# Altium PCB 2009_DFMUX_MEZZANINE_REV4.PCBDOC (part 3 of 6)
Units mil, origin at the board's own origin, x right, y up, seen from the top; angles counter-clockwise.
Board outline 4922.86 x 3627.76 mil, 6 copper layers (Top Layer, Internal Plane 1, Mid-Layer 1, Internal Plane 2, Mid-Layer 2, Bottom Layer); 519 components, 606 nets, 2175 pads, 757 vias.
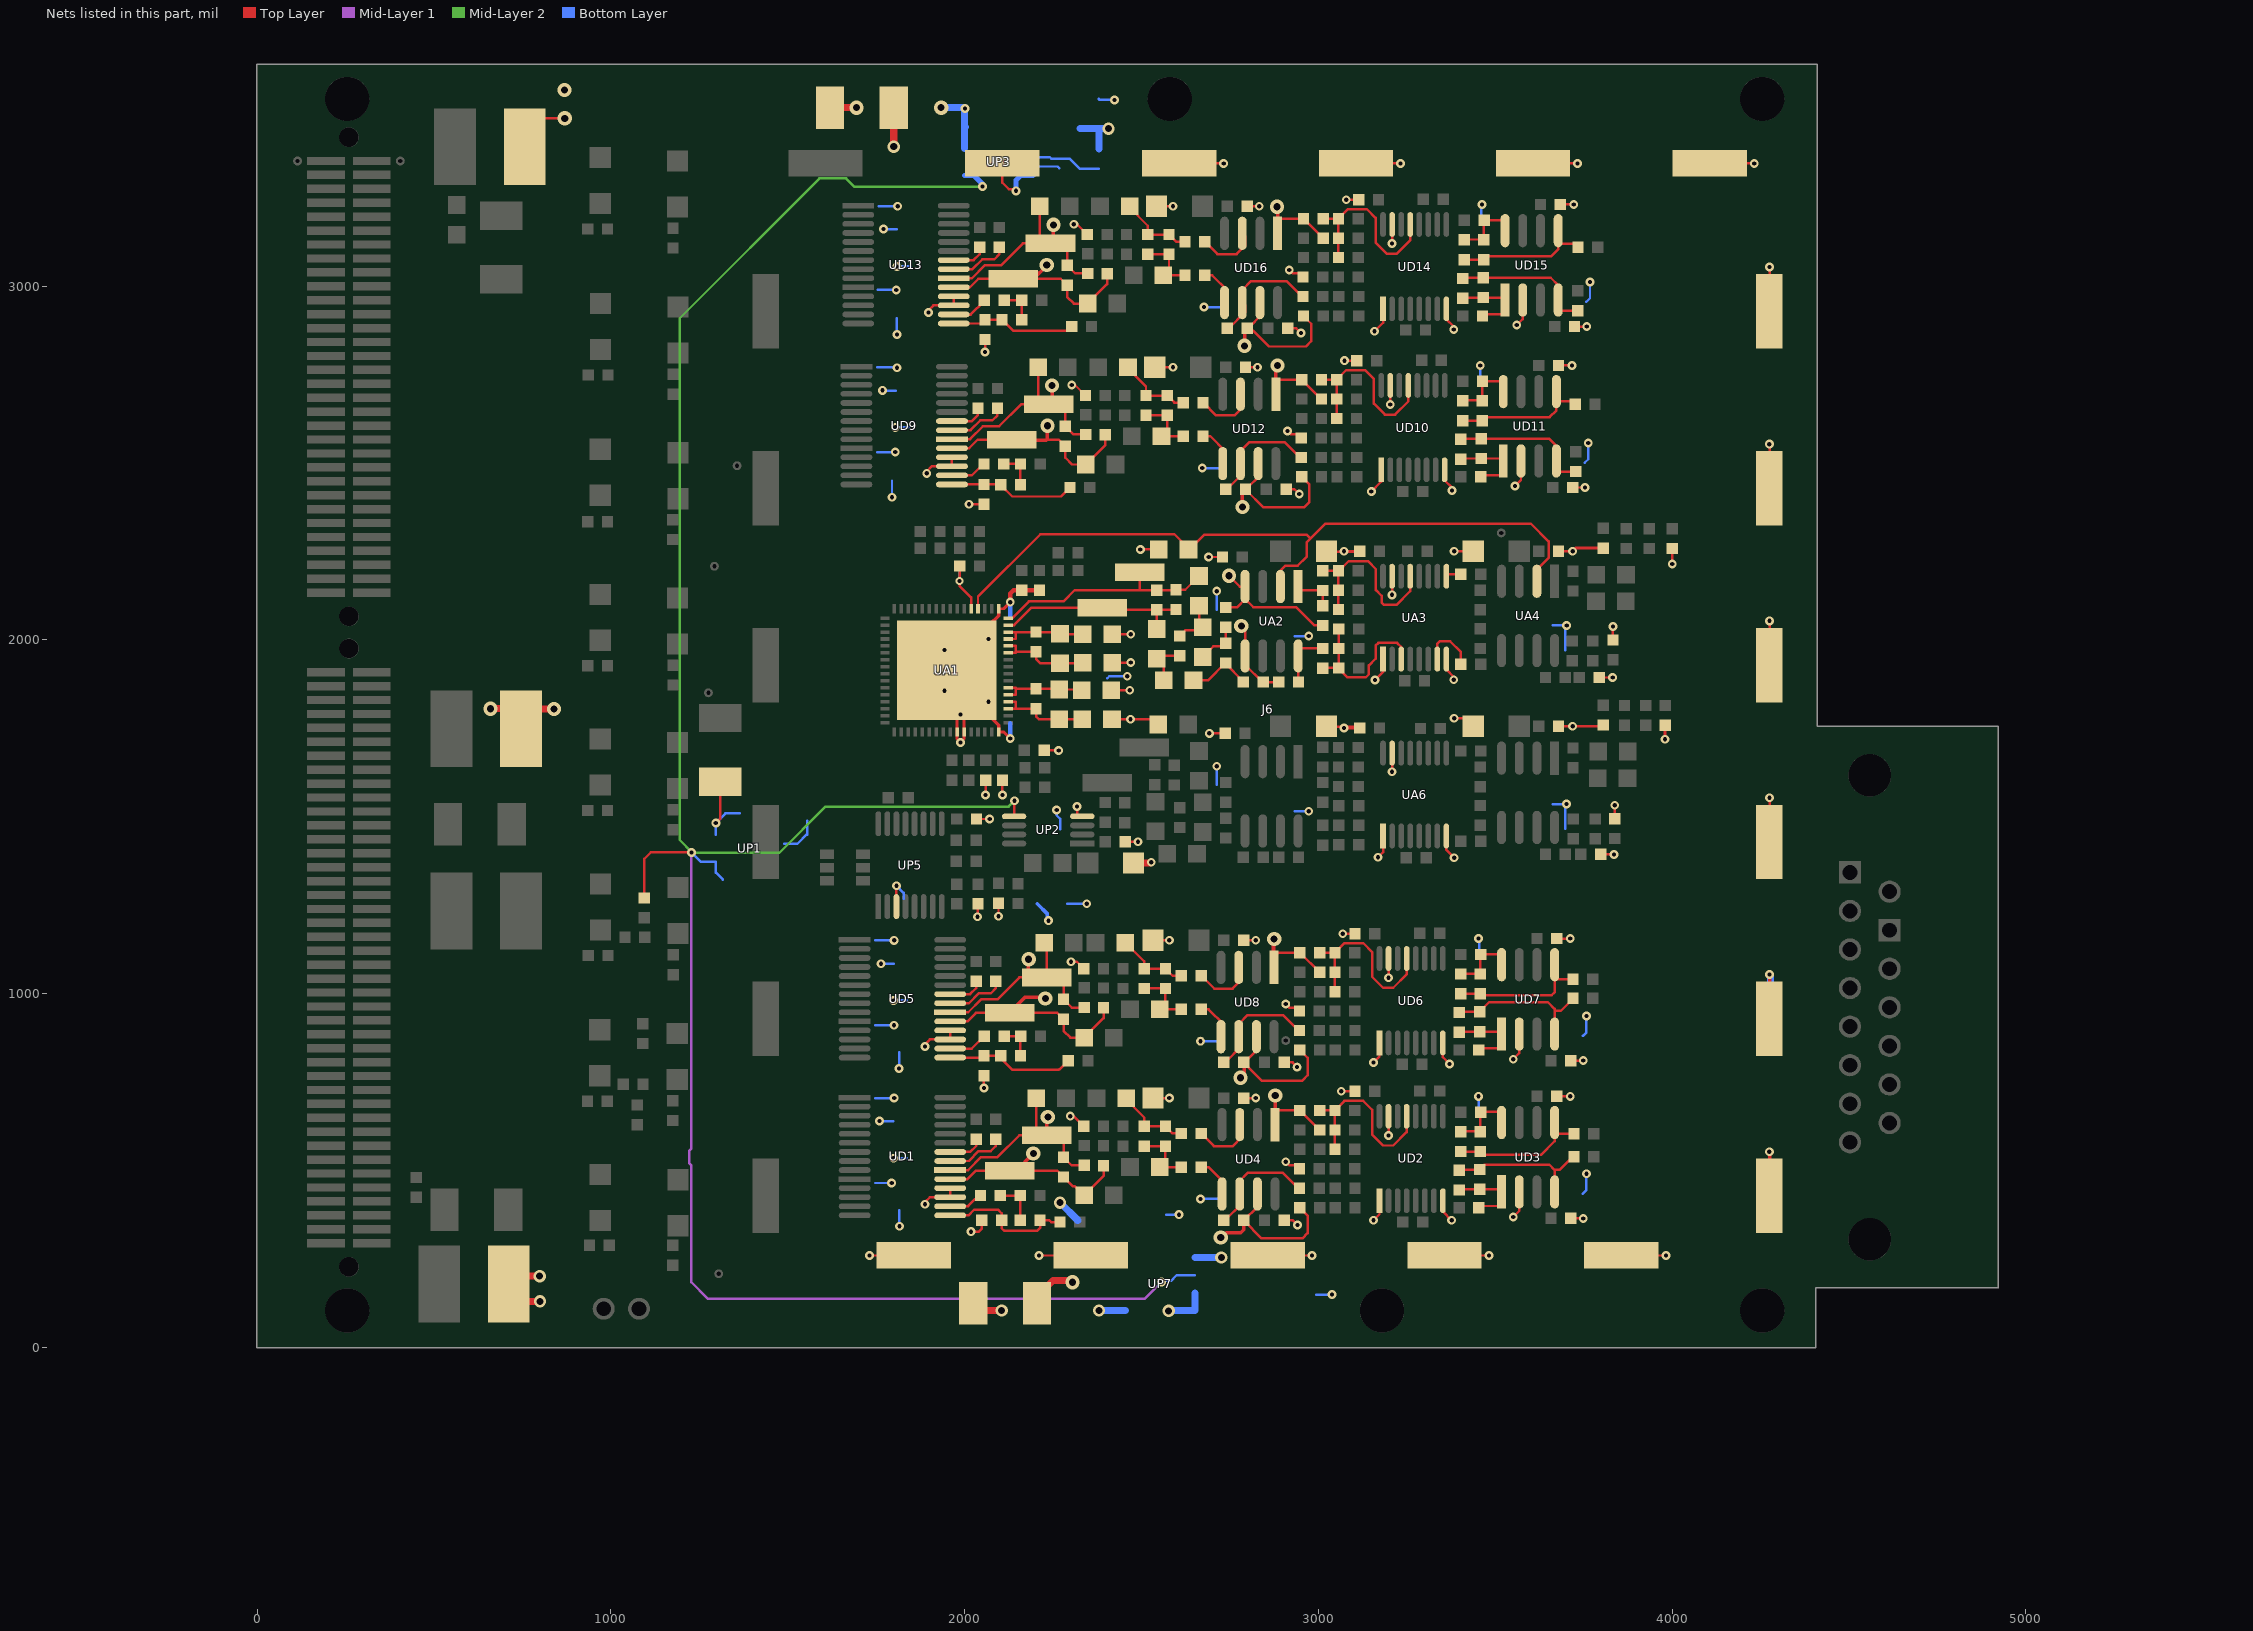
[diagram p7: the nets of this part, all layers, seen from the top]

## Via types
v1: diameter 25, hole 12, Top Layer to Bottom Layer, 692 vias
v2: diameter 40, hole 20, Top Layer to Bottom Layer, 39 vias
v3: diameter 35, hole 20, Top Layer to Bottom Layer, 23 vias
v4: diameter 22, hole 12, Top Layer to Bottom Layer, 3 vias

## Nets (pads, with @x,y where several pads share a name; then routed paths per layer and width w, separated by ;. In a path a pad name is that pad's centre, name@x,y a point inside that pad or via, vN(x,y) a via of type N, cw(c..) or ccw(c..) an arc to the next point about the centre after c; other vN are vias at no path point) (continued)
GND_SIGNAL: CA1.2 CA2.2 CA3.2 CA4.2 CA5.2 CA11.1 CA14.1 CA15.2 CA16.2 CA17.1 CA18.2 CA19.1 CA22.1 CA23.2 CA24.2 CA27.2 CA31.2 CA32.2 CA34.1 CA35.1 CA36.2 CA37.2 CA38.2 CA39.1 CA40.2 CA41.2 CA42.2 CA43.1 CD1.2 CD2.1 CD3.2 CD4.1 CD6.2 CD14.1 CD15.2 CD17.2 CD19.2 CD20.2 CD21.2 CD22.1 CD23.2 CD24.1 CD26.2 CD34.1 CD35.2 CD37.2 CD39.2 CD40.2 CD41.2 CD42.1 CD43.2 CD44.1 CD46.2 CD54.1 CD55.2 CD57.2 CD59.2 CD60.2 CD61.2 CD62.1 CD63.2 CD64.1 CD66.2 CD74.1 CD75.2 CD77.2 CD79.2 CD80.2 CD81.2 CD82.2 CD83.2 CD84.2 CD85.2 CD86.2 CD87.2 CD88.2 CD89.2 CD90.2 CD91.1 CD92.2 CD93.1 CD94.2 CD95.1 CD96.2 CD97.1 CD98.2 CP9.2 CP10.2 CP13.2 CP14.2 CP15.1 CP16.1 CP18.2 CP19.1 CP20.2 CP23.2 CP24.2 CP45.2 CP46.2 J6.1 J6.2 J6.3 J6.4 J6.5 J6.6 J6.7 J6.8 J6.9 J6.10 J6.11 J6.19 J6.20 J6.21 J6.22 J6.23 pad.1@1943.27,1855.87 pad.1@1943.27,1970.87 pad.1@1988.51,1788.64 pad.1@2067.25,1825.06 pad.1@2067.25,2002.22 pad.1@2666.63,865.43 pad.1@2907.63,970.43 pad.1@2939.63,792 RA8.1 RA43.1 RD11.2 RD15.2 RD41.2 RD45.2 RD71.2 RD75.2 RD101.2 RD105.2 RG1.1 RP10.2 RP12.2 RP15.2 RP17.2 RP19.2 RP23.2 RP24.1 RP26.1 RP28.1 RP29.1 RP34.1 RP36.2 RP37.2 RP38.2 RP39.2 RP40.2 RP55.1 RP58.1 UA1.17 UA1.58 UA1.59 UA1.64 UA1.65 UA3.1 UA3.8 UA3.15 UA6.1 UA6.8 UA6.15 UD1.17 UD1.18 UD2.1 UD2.8 UD2.15 UD3.2 UD5.17 UD5.18 UD6.1 UD6.8 UD6.15 UD7.2 UD9.17 UD9.18 UD10.1 UD10.8 UD10.15 UD11.2 UD13.17 UD13.18 UD14.1 UD14.8 UD14.15 UD15.2 UP2.4 UP3.4 UP5.3 UP7.5 | length 15519.3
  Top Layer w7: v1@1731.63,259 v1(1731.13,259.5) J6.11@1856.63,259.5 ; v1(1807.13,1304.87) UP5.3@1807.13,1245.8 ; v1(1887.63,404.43) 1887.83,404.63 1887.83,410.43 1901.63,424.23 UD1.17@1959.03,424.23 UD1.18@1959.03,449.83 ; v1(1887.63,850.43) 1887.83,850.63 1887.83,856.43 1901.63,870.23 ; UD5.18@1959.03,895.83 UD5.17@1959.03,870.23 ; UD9.18@1964.03,2515.83 UD9.17@1964.03,2490.23 1906.63,2490.23 1892.83,2476.43 v1@1892.83,2470.63 ; UD13.18@1969.03,2970.83 UD13.17@1969.03,2945.23 ; UA1.59@1999.48,1740.28 1999.8,1740.6 UA1.59@1999.8,1740.28 ; v1(2012.13,2383) CD57.2@2054.63,2383 ; v1(2017.63,327) 2040.13,327 2048.63,335.5 CD17.2@2048.63,359 ; RP23.2@2033.63,1493.37 v1(2070.63,1493.37) ; v1(2036.63,1217) 2036.63,1222 2037.63,1223 RP28.1@2037.63,1253.37 ; v1(2054.63,733) CD37.2@2054.63,768 ; v1(2057.63,2813.43) CD77.2@2057.63,2849 ; v1(2059.27,1560.87) CA31.2@2059.27,1603.37 ; J6.19@2106.63,3346.5 2106.63,3292 2124.63,3274 v1@2147.63,3274 ; v1(2106.77,1560.87) RA43.1@2106.77,1603.37 ; v1@2297.63,654.43 v1(2298.63,653.43) 2307.63,653.43 RD11.2@2336.63,624.43 RD11.2@2335.63,624.43 ; v1(2302.63,2720.43) 2303.63,2719.43 2312.63,2719.43 RD71.2@2341.63,2690.43 RD71.2@2340.63,2690.43 ; v2(2304.63,184) 2304.63,187 v2@2305.63,188 ; v1@2307.63,3175.43 v1(2308.63,3174.43) 2317.63,3174.43 RD101.2@2346.63,3145.43 RD101.2@2345.63,3145.43 ; v1(2317.63,1529) 2317.63,1505 UP2.4@2321.83,1500.8 ; RD41.2@2335.63,1070.43 RD41.2@2336.63,1070.43 2317.07,1090 ; CD2.1@2532.63,704.43 v1(2578.63,704.43) ; CD22.1@2532.63,1150.43 v1(2578.63,1150.43) ; CA35.1@2547.63,1760.43 2532.63,1775.43 v1(2468.63,1775.43) ; v1(2691.63,1735.43) CA24.2@2736.63,1735.43 ; v1@2731.63,3347 v1(2732.13,3346.5) ; CD40.2@2903.63,805.43 2927.2,805.43 2940.63,792 pad.1@2939.63,792 ; pad.1@2907.63,970.43 2917.63,960.43 RD45.2@2936.63,960.43 ; v1(2912.63,2590.43) 2922.63,2580.43 2941.63,2580.43 RD75.2@2951.63,2570.43 ; v1@2939.63,346 v1(2940.63,346) 2927.2,359.43 ; v1@2944.63,2412 v1(2945.63,2412) 2932.2,2425.43 ; RD15.2@2946.63,504.43 2936.63,514.43 2917.63,514.43 ; RD105.2@2956.63,3025.43 2946.63,3035.43 2927.63,3035.43 ; CA23.2@3022.63,1755.43 3022.63,1754.43 3116.63,1754.43 CD82.2@3116.63,1750.43 ; CA3.2@3022.63,2250.43 3022.63,2249.43 3116.63,2249.43 CD81.2@3116.63,2250.43 ; v1@3063.63,723 v1(3064.63,724) ; v1(3068.63,1169) CD26.2@3103.63,1169 ; v1(3149.63,2419) 3177.63,2447 UD10.1@3177.63,2480.43 ; v1@3158.63,2873 v1(3158.63,2872) 3182.63,2896 UD14.1@3182.63,2935.43 ; v1@3164.2,1881 v1@3168.63,1885.43 ; UA3.1@3182.63,1945.43 3182.63,1909 v1(3159.63,1886) ; v1(3198.22,598.85) UD2.15@3198.22,653.02 ; v1(3203.22,2664.85) UD10.15@3203.22,2719.02 ; v1@3208.05,1627.02 v1(3208.22,1627.02) UA6.15@3208.22,1679.68 ; UA3.15@3208.22,2179.68 v1(3208.22,2127.02) ; v1(3208.22,3119.85) UD14.15@3208.22,3174.02 ; UD2.8@3351.72,414.43 UD2.8@3351.72,383.92 ; UD6.8@3351.72,860.43 3351.72,819.92 v1(3370.63,801) ; UD14.8@3361.72,2935.43 3361.72,2905.87 3382.58,2885 v1(3382.58,2877) ; UA3.8@3361.77,1945.43 3361.77,1915.87 3382.63,1895 v1(3382.63,1887) ; v1(3377.58,2422) 3377.58,2430 UD10.8@3356.72,2450.87 ; v1(3383.63,1384) 3361.77,1405.87 ; v1(3383.63,2250.43) CA36.2@3437.63,2250.43 ; v1@3384.63,1779 v1(3383.63,1778) 3413.63,1778 CA40.2@3437.63,1755.43 ; v1@3481.63,260 v1(3482.13,259.5) ; v1(3550.63,368.43) 3567.63,385.43 UD3.2@3567.63,439.43 ; UD11.2@3572.63,2505.43 3572.63,2451.43 ; UD15.2@3577.63,2960.43 3577.63,2906.43 ; J6.22@3606.63,3346.5 v1(3732.13,3346.5) v1@3731.63,3347 ; CD85.2@3673.63,1155.43 v1(3711.63,1155.43) ; CD89.2@3683.63,3230.43 v1(3721.63,3230.43) ; RP29.1@3793.63,1893.37 v1(3831.63,1893.37) ; RP34.1@3797.63,1393.37 v1(3835.63,1393.37) v1@3834.63,1394.37 ; RP58.1@3805,1759 3801.43,1755.43 v1(3718.63,1755.43) ; CP18.2@3832.63,1999.37 v1(3832.63,2037.37) ; CP20.2@3837.63,1494.37 v1(3837.63,1532.37) ; J6.23@4106.63,3346.5 v1(4232.13,3346.5) v1@4231.63,3347 ; v1(4274.63,553) v1@4275.13,553.5 ; v1@4274.63,1553 v1(4275.13,1553.5) J6.4@4275.13,1428 ; v1@4274.63,2053 v1(4275.13,2053.5) J6.3@4275.13,1928 ; J6.2@4275.13,2428 v1@4275.13,2553.5 ; UP5.3@1807.13,1245.8 1807.63,1245.3 UP5.3@1807.13,1245.8 ; v1@1892.83,2470.63 v1(1892.63,2470.43) v1@1892.83,2470.63 ; v1@1897.83,2925.63 v1(1897.63,2925.43) v1@1897.83,2925.63 ; v1@1897.83,2925.63 1897.83,2931.43 1911.63,2945.23 ; 1901.63,870.23 UD5.17@1959.03,870.23 ; 1901.63,870.23 UD5.17@1959.03,870.23 ; 1911.63,2945.23 UD13.17@1969.03,2945.23 ; 1911.63,2945.23 UD13.17@1969.03,2945.23 ; CA27.2@2224.63,1687.37 v1(2265.63,1687.37) ; CA27.2@2224.63,1687.37 v1(2265.63,1687.37) ; CA27.2@2224.63,1687.37 v1(2265.63,1687.37) ; 2317.07,1090 v1(2300.63,1090) 2317.07,1090 ; UP2.4@2321.83,1500.8 UP2.4@2332.63,1500.8 UP2.4@2321.83,1500.8 ; v1(2468.63,1775.43) CA22.1@2416.63,1775.43 v1(2468.63,1775.43) ; v1(2732.13,3346.5) 2606.63,3346.5 v1(2732.13,3346.5) ; CD1.2@2788.63,704.43 v1(2822.63,704.43) ; CD1.2@2788.63,704.43 v1(2822.63,704.43) ; CD1.2@2788.63,704.43 v1(2822.63,704.43) ; 2917.63,514.43 v1(2907.63,524.43) 2917.63,514.43 ; 2927.2,359.43 CD20.2@2903.63,359.43 2927.2,359.43 ; 2927.63,3035.43 v1(2917.63,3045.43) 2927.63,3035.43 ; 2932.2,2425.43 CD60.2@2908.63,2425.43 2932.2,2425.43 ; RD45.2@2936.63,960.43 RD45.2@2946.63,950.43 RD45.2@2936.63,960.43 ; 2937.2,2880.43 v1(2950.63,2867) ; 2937.2,2880.43 CD80.2@2913.63,2880.43 2937.2,2880.43 ; v1(2950.63,2867) 2949.63,2867 v1(2950.63,2867) ; v1(2982.13,259.5) 2981.63,260 v1(2982.13,259.5) ; v1(2982.13,259.5) 2856.63,259.5 v1(2982.13,259.5) ; v1(3064.63,724) CD6.2@3103.63,724 v1(3064.63,724) ; CD82.2@3116.63,1750.43 v1(3072.63,1750.43) CD82.2@3116.63,1750.43 ; CD81.2@3116.63,2250.43 v1(3072.63,2250.43) CD81.2@3116.63,2250.43 ; v1(3159.63,1886) 3154.63,1881 v1(3159.63,1886) ; 3172.63,376 v1(3155.63,359) 3172.63,376 ; 3172.63,376 UD2.1@3172.63,414.43 3172.63,376 ; 3172.63,822 UD6.1@3172.63,860.43 3172.63,822 ; 3172.63,822 v1(3155.63,805) 3172.63,822 ; 3182.63,1399.43 UA6.1@3182.63,1445.43 3182.63,1399.43 ; 3182.63,1399.43 v1(3168.63,1385.43) 3182.63,1399.43 ; v1(3208.22,2127.02) 3208.05,2127.02 v1(3208.22,2127.02) ; v1(3232.13,3346.5) 3231.63,3347 v1(3232.13,3346.5) ; v1(3232.13,3346.5) 3106.63,3346.5 v1(3232.13,3346.5) ; UD2.8@3351.72,383.92 v1(3376.63,359) UD2.8@3351.72,383.92 ; UD10.8@3356.72,2450.87 UD10.8@3356.72,2480.43 UD10.8@3356.72,2450.87 ; 3361.77,1405.87 UA6.8@3361.77,1445.43 3361.77,1405.87 ; v1(3482.13,259.5) 3356.63,259.5 v1(3482.13,259.5) ; 3567.63,831.43 v1(3550.63,814.43) 3567.63,831.43 ; 3567.63,831.43 UD7.2@3567.63,885.43 3567.63,831.43 ; 3572.63,2451.43 v1(3555.63,2434.43) 3572.63,2451.43 ; 3577.63,2906.43 v1(3560.63,2889.43) 3577.63,2906.43 ; v1(3718.63,1755.43) CA41.2@3678.63,1755.43 v1(3718.63,1755.43) ; v1(3831.63,1893.37) 3830.63,1894.37 v1(3831.63,1893.37) ; v1(3832.63,2037.37) 3831.63,2036.37 v1(3832.63,2037.37) ; v1(3837.63,1532.37) 3836.63,1531.37 v1(3837.63,1532.37) ; v1(3982.13,259.5) 3981.63,260 v1(3982.13,259.5) ; v1(3982.13,259.5) 3856.63,259.5 v1(3982.13,259.5) ; v1@4275.13,2553.5 v1(4274.63,2553) v1@4275.13,2553.5 ; v1(4275.13,3053.5) 4274.63,3053 v1(4275.13,3053.5) ; v1(4275.13,3053.5) 4275.13,2928 v1(4275.13,3053.5) ; v1(2095.63,1218.37) RP26.1@2095.63,1255.37 v1(2095.63,1218.37) ; v1(2210.13,259.5) 2356.63,259.5 v1(2210.13,259.5) ; CA19.1@2414.63,1857.43 v1(2466.63,1857.43) CA19.1@2414.63,1857.43 ; CA14.1@2417.63,1935.43 v1(2469.63,1935.43) CA14.1@2417.63,1935.43 ; CA11.1@2417.63,2015.43 v1(2469.63,2015.43) CA11.1@2417.63,2015.43 ; RP10.2@2453.63,1429 v1(2489.63,1429) RP10.2@2453.63,1429 ; v1(2496.63,2255.43) CA1.2@2548.63,2255.43 v1(2496.63,2255.43) ; v1@2525.63,1369 v1(2527.63,1371) v1@2525.63,1369 ; CD42.1@2537.63,2770.43 v1(2588.63,2770.43) CD42.1@2537.63,2770.43 ; CD62.1@2542.63,3225.43 v1(2588.63,3225.43) CD62.1@2542.63,3225.43 ; v1(2689.63,2234) CA5.2@2728.63,2234 v1(2689.63,2234) ; CD21.2@2788.63,1150.43 v1(2822.63,1150.43) CD21.2@2788.63,1150.43 ; CD41.2@2793.63,2770.43 v1(2827.63,2770.43) CD41.2@2793.63,2770.43 ; CD61.2@2798.63,3225.43 v1(2832.63,3225.43) CD61.2@2798.63,3225.43 ; v1(3073.63,2789) CD46.2@3108.63,2789 v1(3073.63,2789) ; v1(3078.63,3244) CD66.2@3113.63,3244 v1(3078.63,3244) ; v1(3198.22,1044.85) UD6.15@3198.22,1099.02 v1(3198.22,1044.85) ; CD83.2@3673.63,709.43 v1(3711.63,709.43) CD83.2@3673.63,709.43 ; CA37.2@3678.63,2250.43 v1(3718.63,2250.43) CA37.2@3678.63,2250.43 ; CD87.2@3678.63,2775.43 v1(3716.63,2775.43) CD87.2@3678.63,2775.43 ; CD84.2@3713.63,364.43 v1(3748.63,364.43) CD84.2@3713.63,364.43 ; CD86.2@3713.63,810.43 v1(3748.63,810.43) CD86.2@3713.63,810.43 ; CD88.2@3718.63,2430.43 v1(3753.63,2430.43) CD88.2@3718.63,2430.43 ; CD90.2@3723.63,2885.43 v1(3758.63,2885.43) CD90.2@3723.63,2885.43 ; v1@4274.63,1053 v1(4275.13,1053.5) v1@4274.63,1053
  Top Layer w8: UA1.65@1978.66,1787.76 UA1.58@1978.66,1739.43 1978.66,1719.74 v1(1988.51,1709.9) 1998.35,1719.74 UA1.59@1998.35,1739.43 UA1.65@1998.35,1786.79 ; UA1.64@2096.77,1739.43 2110.45,1739.43 v1(2129,1720.87) ; UA1.17@2096.77,2087.85 2110.45,2087.85 v1(2129,2106.41) ; v1(3718.63,2250.43) 3727.2,2259 RP55.1@3805,2259 ; v1(3980,1719) CP46.2@3980,1758 v1(3980,1719) ; v1(4000,2214) CP45.2@4000,2258 v1(4000,2214)
  Top Layer w10: UA1.65@2071.77,2043.37 2096.77,2068.37 UA1.17@2096.77,2087.85 ; UA1.65@2074.27,1780.87 2096.77,1758.36 UA1.64@2096.77,1739.43 ; v1(2145,3269) v1@2147.63,3274 ; J6.6@4275.13,428 4275.13,553.5 J6.6@4275.13,428 ; J6.5@4275.13,928 v1(4275.13,1053.5) J6.5@4275.13,928
  Top Layer w12: v1(2129,2106.41) 2129,2130.6 2138.27,2139.87 CA2.2@2161.77,2139.87 RA8.1@2211.77,2139.87
  Top Layer w20: v3(1799.63,3394) CP13.2@1799.63,3504 ; CP15.1@2204.63,124 2204.63,143.63 2250,189 2304.63,189 v2@2305.63,188 ; CP10.2@2477.63,1369 v1@2525.63,1369 ; CP10.2@2477.63,1369 v1@2525.63,1369 ; CP10.2@2477.63,1369 v1@2525.63,1369
  Bottom Layer w7: CD34.1@1747.63,910.43 v1(1800.57,910.43) ; v1@1760.63,640.37 v1(1759.63,639.37) CD4.1@1797.63,639.37 ; v1(1763.63,1084) CD24.1@1799.63,1084 ; v1(1794.63,2403) RP37.2@1794.63,2449 ; v1(1798.63,534.43) CD15.2@1836.63,534.43 ; v1(1798.63,980.43) CD35.2@1836.63,980.43 ; v1(1800.63,1150.37) v1@1800.57,1150.43 ; v1@1801.07,704 v1(1800.63,704.43) ; v1(1803.63,2600.43) CD55.2@1841.63,2600.43 ; CD44.1@1804.63,2704 v1@1766.63,2704 ; v1(1807.13,1304.87) 1827.63,1284.37 CP19.1@1827.63,1268.37 ; v1(1808.63,3055.43) CD75.2@1846.63,3055.43 ; v1(1810.63,3225.37) v1@1810.57,3225.43 ; v1(1814.63,788) RP39.2@1814.63,834 ; CP23.2@2270,1464 2270,1494 2260,1504 ; CP24.2@2290,1254 v1(2345,1254) ; CP14.2@2322.63,3449 2326.63,3445 ; RP17.2@2378.63,3529 2381.63,3526 v1(2423.63,3526) ; v1(2666.63,419.43) CD19.2@2722.63,419.43 ; pad.1@2666.63,865.43 CD39.2@2722.63,865.43 ; v1(2671.63,2485.43) CD59.2@2727.63,2485.43 ; CA34.1@2712.63,1590.43 v1(2712.63,1642.43) ; CA17.1@2712.63,2085.43 v1(2712.63,2137.43) ; CA32.2@2933.63,1515.43 v1(2972.63,1515.43) ; CA16.2@2933.63,2010.43 v1(2972.63,2010.43) ; RP19.2@2993.63,149 v1(3038.63,149) ; v1(3452.63,709.43) 3452.63,656 CD91.1@3454.63,654 ; v1(3452.63,1155.43) 3454.63,1153.43 CD93.1@3454.63,1099 ; 3457.63,2721 v1(3457.63,2775.43) ; CD95.1@3459.63,2719 3461.63,2717 ; CD97.1@3459.63,3174 3459.63,3227.43 v1(3462.63,3230.43) ; CA38.2@3662.63,2040.43 3693.63,2040.43 v1@3697.63,2036.43 ; CA43.1@3697.63,1465.43 3697.63,1531.43 v1@3701.63,1535.43 ; CA39.1@3697.63,1970.43 v1@3697.63,2036.43 ; CD92.2@3747.63,434.43 3757.63,444.43 v1(3757.63,490.43) ; CD96.2@3752.63,2500.43 3762.63,2510.43 v1(3762.63,2556.43) ; v1(4274.63,553) v1@4278,556.37 ; v1@4274.63,1053 4271,1053 v1@4278,1046 ; v1@4275,1054 v1@4278,1051 ; v1@1766.63,2704 v1(1767.63,2705) v1@1766.63,2704 ; v1@1769.63,3160.37 v1(1770.63,3161.37) v1@1769.63,3160.37 ; v1@1769.63,3160.37 CD64.1@1807.63,3160.37 v1@1769.63,3160.37 ; v1(1800.57,910.43) 1800.63,910.37 v1(1800.57,910.43) ; v1@1800.57,1150.43 CD23.2@1747.63,1150.43 v1@1800.57,1150.43 ; v1(1800.63,704.43) CD3.2@1747.63,704.43 v1(1800.63,704.43) ; v1@1806.2,2989 v1(1806.63,2988.57) v1@1806.2,2989 ; v1@1806.2,2989 CD74.1@1754.63,2989 v1@1806.2,2989 ; v1@1807.2,2770.43 v1(1808.63,2769) v1@1807.2,2770.43 ; v1@1807.2,2770.43 CD43.2@1752.63,2770.43 v1@1807.2,2770.43 ; v1@1810.57,3225.43 CD63.2@1757.63,3225.43 v1@1810.57,3225.43 ; 2260,1504 v1(2260,1519) 2260,1504 ; 2408.63,1897 v1(2459.63,1897) 2408.63,1897 ; 2408.63,1897 RP12.2@2402.63,1891 2408.63,1897 ; v1@3697.63,2036.43 v1(3701.63,2040.43) v1@3697.63,2036.43 ; v1@3701.63,1535.43 CA42.2@3662.63,1535.43 v1@3701.63,1535.43 ; 3757.63,890.43 v1(3757.63,936.43) 3757.63,890.43 ; 3757.63,890.43 CD94.2@3747.63,880.43 3757.63,890.43 ; 3767.63,2965.43 v1(3767.63,3011.43) 3767.63,2965.43 ; 3767.63,2965.43 CD98.2@3757.63,2955.43 3767.63,2965.43 ; CD14.1@1747.63,464.43 v1(1793.63,464.43) CD14.1@1747.63,464.43 ; CD54.1@1752.63,2530.43 v1(1803.63,2530.43) CD54.1@1752.63,2530.43 ; v1(1808.63,2863) RP36.2@1808.63,2909 v1(1808.63,2863) ; v1(1815.63,342) RP40.2@1815.63,388 v1(1815.63,342) ; RP24.1@2569.63,375 v1(2605.63,375) RP24.1@2569.63,375 ; v1(2676.63,2940.43) CD79.2@2732.63,2940.43 v1(2676.63,2940.43)
  Bottom Layer w10: v1(2237,1206) 2234,1203 2234,1225 ; v1@4274.63,1053 4274.63,1053.63 v1@4275,1054 ; 2234,1225 CP9.2@2205,1254 2234,1225
  Bottom Layer w12: v1(2129,1720.87) CA18.2@2129,1763.91 ; CA4.2@2129,2063.37 v1(2129,2106.41)
  Bottom Layer w15: 2145,3299 v1(2145,3269) 2145,3299 ; 2145,3299 2158.2,3312.2 ; 2158.2,3312.2 UP3.4@2192.63,3312.2 2158.2,3312.2
  Bottom Layer w20: pad.1@1943.27,1855.87 RP38.2@1943.27,1913.37 ; pad.1@1943.27,1970.87 RP38.2@1943.27,1913.37 ; CA15.2@2035.77,1913.37 RP38.2@1943.27,1913.37 ; 2326.63,3445 2379.63,3445 ; v3(2406.63,3445) 2379.63,3445 ; UP7.5@2650.63,254 v3(2725.63,254) ; v1@4278,1051 v1@4278,1046 ; 2379.63,3445 RP15.2@2379.63,3387 2379.63,3445 ; v1@4278,1046 RG1.1@4278,962 v1@4278,1046 ; v3(2269.63,409) CP16.1@2319.63,359 v3(2269.63,409)
  other v1: 3701.13,1535.43
N02025: CD68.2 UD13.22 | length 99.7
  Top Layer w7: UD13.22@1969.03,3073.23 2025.43,3073.23 2042.63,3090.43 CD68.2@2042.63,3109.43
N02025_5443: CD48.2 UD9.22 | length 99.7
  Top Layer w7: UD9.22@1964.03,2618.23 2020.43,2618.23 2037.63,2635.43 CD48.2@2037.63,2654.43
N02025_5891: CD28.2 UD5.22 | length 99.7
  Top Layer w7: UD5.22@1959.03,998.23 2015.43,998.23 2032.63,1015.43 CD28.2@2032.63,1034.43
N02025_6339: CD8.2 UD1.22 | length 99.7
  Top Layer w7: UD1.22@1959.03,552.23 2015.43,552.23 2032.63,569.43 CD8.2@2032.63,588.43
N02076: CD9.2 UD1.21 | length 165.9
  Top Layer w7: UD1.21@1959.03,526.63 2011.83,526.63 2039.63,554.43 2073.63,554.43 2087.63,568.43 CD9.2@2087.63,588.43
N02076_2990: CD69.2 UD13.21 | length 165.9
  Top Layer w7: UD13.21@1969.03,3047.63 2021.83,3047.63 2049.63,3075.43 2083.63,3075.43 2097.63,3089.43 CD69.2@2097.63,3109.43
N02076_5385: CD49.2 UD9.21 | length 165.9
  Top Layer w7: UD9.21@1964.03,2592.63 2016.83,2592.63 2044.63,2620.43 2078.63,2620.43 2092.63,2634.43 CD49.2@2092.63,2654.43
N02076_5833: CD29.2 UD5.21 | length 165.9
  Top Layer w7: UD5.21@1959.03,972.63 2011.83,972.63 2039.63,1000.43 2073.63,1000.43 2087.63,1014.43 CD29.2@2087.63,1034.43
N03097: CD77.1 RD118.2 RD120.1 UD13.15 | length 355.7
  Top Layer w7: UD13.15@1969.03,2894.03 2046.67,2894.03 CD77.1@2057.63,2905 RD118.2@2105.63,2905 2136.63,2874 2291.2,2874 RD120.1@2302.63,2885.43
N03097_5373: CD57.1 RD88.2 RD90.1 UD9.15 | length 358.2
  Top Layer w7: UD9.15@1964.03,2439.03 CD57.1@2054.63,2439 2100.63,2439 RD88.2@2101.63,2438 2134.63,2405 2272.2,2405 RD90.1@2297.63,2430.43
N03097_5821: CD37.1 RD58.2 RD60.1 UD5.15 | length 369.6
  Top Layer w7: UD5.15@1959.03,819.03 1962.63,815.43 1965.2,818 2048.63,818 CD37.1@2054.63,824 RD58.2@2101.63,824 2101.63,818 2135.63,784 2266.07,784 2267.63,785.43 RD60.1@2292.63,810.43
N03097_6269: CD17.1 RD28.2 RD30.1 UD1.15 | length 394.1
  Top Layer w7: UD1.15@1959.03,373.03 2011.17,373.03 2027.13,389 2094.63,389 2104.63,379 CD17.1@2104.63,359 2104.63,336.5 2112.13,329 2204.63,329 2213.13,337.5 RD28.2@2213.13,359 2239.63,359 2244.63,354 RD30.1@2269.63,354
N04051: RD2SET4.1 UD13.16 | length 105.6
  Top Layer w7: UD13.16@1969.03,2919.63 1970.03,2918.43 1970.6,2919 2016.63,2919 2055.63,2958 RD2SET4.1@2055.63,2960
N04051_5452: RD2SET3.1 UD9.16 | length 104
  Top Layer w7: UD9.16@1964.03,2464.63 1964.4,2465 2020.63,2465 2052.63,2497 RD2SET3.1@2054.63,2497
N04051_5900: RD2SET2.1 UD5.16 | length 111.9
  Top Layer w7: UD5.16@1959.03,844.63 1960.03,843.43 1960.6,844 2019.63,844 2054.63,879 RD2SET2.1@2055.63,879
N04051_6348: RD2SET1.1 UD1.16 | length 104
  Top Layer w7: UD1.16@1959.03,398.63 1959.4,399 2009.63,399 2029.63,419 2044.63,419 RD2SET1.1@2044.63,429
N04200: RD2SET4.2 RD110.1 RD118.1 | length 105
  Top Layer w7: RD2SET4.2@2111.63,2960 RD110.1@2161.63,2960 RD118.1@2161.63,2905
N04200_5371: RD2SET3.2 RD80.1 RD88.1 | length 107
  Top Layer w7: RD2SET3.2@2109.63,2497 RD2SET3.2@2110.63,2497 RD80.1@2157.63,2497 RD88.1@2157.63,2438
N04200_5819: RD2SET2.2 RD50.1 RD58.1 | length 103.4
  Top Layer w7: RD2SET2.2@2110.63,879 RD2SET2.2@2111.63,879 RD50.1@2158.63,879 2157.63,878 RD58.1@2157.63,824
N04200_6267: RD2SET1.2 RD20.1 RD28.1 | length 126.5
  Top Layer w7: RD2SET1.2@2100.63,429 RD20.1@2157.13,429 RD28.1@2157.13,359
N07701: CD70.1 JD4.2 LD13.1 RD100.1 UD13.20 | length 655.6
  Top Layer w7: UD13.20@1969.03,3022.03 2020.23,3022.03 2056.63,3058.43 2102.63,3058.43 2164.63,3120.43 JD4.2@2221.63,3120.43 ; LD13.1@2212.63,3225.43 2212.63,3129.43 JD4.2@2221.63,3120.43 ; RD100.1@2347.63,3035.43 2312.63,3035.43 CD70.1@2289.63,3058.43 2289.63,3120.43 JD4.2@2242.63,3120.43 JD4.2@2221.63,3120.43
  Top Layer w10: JD4.2@2242.63,3120.43 2251,3128.8 v2(2251,3173)
N07701_5419: CD50.1 JD3.2 LD9.1 RD70.1 UD9.20 | length 662.2
  Top Layer w7: UD9.20@1964.03,2567.03 2015.23,2567.03 2051.63,2603.43 2097.63,2603.43 2159.63,2665.43 JD3.2@2216.63,2665.43 ; LD9.1@2207.63,2770.43 2207.63,2674.43 JD3.2@2216.63,2665.43 ; JD3.2@2237.63,2665.43 JD3.2@2216.63,2665.43 ; JD3.2@2246.43,2665.43 2284.63,2665.43 CD50.1@2284.63,2603.43 2307.63,2580.43 RD70.1@2342.63,2580.43
  Top Layer w10: v2(2247,2719) 2247,2666 JD3.2@2246.43,2665.43 ; JD3.2@2246.43,2665.43 JD3.2@2237.63,2665.43 JD3.2@2246.43,2665.43
N07701_5867: CD30.1 JD2.2 LD5.1 RD40.1 UD5.20 | length 654.5
  Top Layer w7: UD5.20@1959.03,947.03 2010.23,947.03 2046.63,983.43 2092.63,983.43 2154.63,1045.43 JD2.2@2203.57,1045.43 ; LD5.1@2224.63,1144 2232.63,1136 JD2.2@2232.63,1045.43 2279.63,1045.43 CD30.1@2279.63,983.43 2302.63,960.43 RD40.1@2337.63,960.43
  Top Layer w10: v2(2181,1097) 2180,1096 2180,1069 2203.57,1045.43 JD2.2@2232.63,1045.43
N07701_6315: CD10.1 JD1.2 LD1.1 RD10.1 UD1.20 | length 652.2
  Top Layer w7: UD1.20@1959.03,501.03 2010.23,501.03 2046.63,537.43 2092.63,537.43 2154.63,599.43 JD1.2@2211.63,599.43 ; LD1.1@2202.63,704.43 2202.63,608.43 JD1.2@2211.63,599.43 ; RD10.1@2337.63,514.43 2302.63,514.43 CD10.1@2279.63,537.43 2279.63,599.43 JD1.2@2232.63,599.43 JD1.2@2211.63,599.43
  Top Layer w10: JD1.2@2232.63,599.43 2232.63,648.63 v2(2235,651)
N07959: CD10.2 JD1.1 LD3.1 RD16.2 UD1.19 | length 618.4
  Top Layer w7: UD1.19@1959.03,475.43 2007.63,475.43 2031.63,499.43 JD1.1@2127.63,499.43 ; RD16.2@2392.63,513.43 2392.63,484.43 LD3.1@2337.63,429.43 2311.63,455 2306.2,455 2279.63,481.1 CD10.2@2279.63,481.43 2261.63,499.43 JD1.1@2145.43,499.43 ; JD1.1@2127.63,499.43 JD1.1@2145.43,499.43 ; JD1.1@2127.63,499.43 JD1.1@2145.43,499.43
  Top Layer w10: JD1.1@2140,494 2145.43,499.43 v2(2194,548)
N07959_3010: CD70.2 JD4.1 LD15.1 RD106.2 UD13.19 | length 599.2
  Top Layer w7: UD13.19@1969.03,2996.43 2015.07,2996.43 2039.07,3020.43 JD4.1@2137.63,3020.43 2194.43,3020.43 2271.63,3020.43 CD70.2@2289.63,3002.43 2289.63,2969.43 2308.63,2950.43 LD15.1@2347.63,2950.43 2402.63,3005.43 RD106.2@2402.63,3034.43
  Top Layer w10: JD4.1@2194.43,3020.43 2233,3059 v2(2232,3059)
N07959_5408: CD50.2 JD3.1 LD11.1 RD76.2 UD9.19 | length 735.1
  Top Layer w7: UD9.19@1964.03,2541.43 2012.63,2541.43 2036.63,2565.43 JD3.1@2132.63,2565.43 ; RD76.2@2397.63,2579.43 2397.63,2550.43 LD11.1@2342.63,2495.43 2303.63,2495.43 2284.63,2514.43 CD50.2@2284.63,2547.43 2266.63,2565.43 2231.43,2565.43 ; JD3.1@2132.63,2565.43 2231.43,2565.43 ; JD3.1@2132.63,2565.43 2231.43,2565.43
  Top Layer w10: JD3.1@2180,2564 2230,2564 2231.43,2565.43 2234,2568 v2(2234,2605)
N07959_5856: CD30.2 JD2.1 LD7.1 RD46.2 UD5.19 | length 664
  Top Layer w7: UD5.19@1959.03,921.43 2007.63,921.43 2031.63,945.43 JD2.1@2127.63,945.43 2261.63,945.43 CD30.2@2279.63,927.43 2279.63,894.43 2298.63,875.43 LD7.1@2337.63,875.43 2392.63,930.43 RD46.2@2392.63,959.43
  Top Layer w10: JD2.1@2127.63,945.43 2127.63,946.63 2170,989 2225,989 v2(2228,986)
N08417: CD11.1 LD2.2 RD9.1 RD14.1 | length 214.4
  Top Layer w7: LD2.2@2456.63,704.43 2456.63,700.43 2507.63,649.43 CD11.1@2507.63,624.43 RD14.1@2567.63,624.43 2587.63,604.43 RD9.1@2612.63,604.43
N08417_3009: CD71.1 LD14.2 RD99.1 RD104.1 | length 214.4
  Top Layer w7: LD14.2@2466.63,3225.43 2466.63,3221.43 2517.63,3170.43 CD71.1@2517.63,3145.43 RD104.1@2577.63,3145.43 2597.63,3125.43 RD99.1@2622.63,3125.43
N08417_5407: CD51.1 LD10.2 RD69.1 RD74.1 | length 214.4
  Top Layer w7: LD10.2@2461.63,2770.43 2461.63,2766.43 2512.63,2715.43 CD51.1@2512.63,2690.43 RD74.1@2572.63,2690.43 2592.63,2670.43 RD69.1@2617.63,2670.43
N08417_5855: CD31.1 LD6.2 RD39.1 RD44.1 | length 222.1
  Top Layer w7: LD6.2@2453.63,1144 2453.63,1147.43 2456.63,1150.43 2456.63,1142 2507.63,1091 CD31.1@2507.63,1070.43 RD44.1@2567.63,1070.43 2587.63,1050.43 RD39.1@2612.63,1050.43
N08612: CA8.1 LA2.2 RA19.1 | length 126.2
  Top Layer w7: LA2.2@2672.63,1951.43 2702.63,1981.43 2728.63,1981.43 CA8.1@2737.63,1990.43 RA19.1@2737.63,2035.43
N08712: CA8.2 LA4.2 RA21.1 | length 186
  Top Layer w7: LA4.2@2646.63,1885.43 2687.63,1885.43 2736.63,1934.43 CA8.2@2737.63,1934.43 2737.63,1932.43 2787.63,1882.43 RA21.1@2787.63,1880.43
N08812: CA10.2 LA3.2 LA4.1 | length 137.6
  Top Layer w7: LA4.1@2562.63,1885.43 2562.63,1926.43 LA3.2@2542.63,1946.43 2550.63,1954.43 CA10.2@2607.63,1954.43
N09123: CA10.1 LA1.2 LA2.1 | length 140.5
  Top Layer w7: CA10.1@2607.63,2010.43 2623.63,2026.43 2663.63,2026.43 LA2.1@2672.63,2035.43 2662.63,2045.43 LA1.2@2662.63,2096.43
N09233: CA9.2 JA1.2 LA3.1 RA20.1 UA1.15 | length 550.1
  Top Layer w7: UA1.15@2123.35,2041.59 2139.99,2041.59 2189.27,2090.87 JA1.2@2389.27,2090.87 2408.63,2084.43 CA9.2@2542.63,2084.43 ; LA3.1@2542.63,2030.43 CA9.2@2542.63,2084.43 ; RA20.1@2597.63,2085.43 2596.63,2084.43 CA9.2@2542.63,2084.43
N09341: CA9.1 JA1.1 LA1.1 RA20.2 UA1.16 | length 639.1
  Top Layer w7: UA1.16@2123.35,2061.28 2134.68,2061.28 2181.77,2108.37 2279.27,2108.37 2311.34,2140.43 2494.27,2140.43 ; JA1.1@2494.27,2190.87 2494.27,2140.43 ; LA1.1@2662.63,2180.43 2623.63,2141.43 RA20.2@2597.63,2141.43 2596.63,2140.43 CA9.1@2542.63,2140.43 2494.27,2140.43
N09563: CD71.2 LD16.2 RD104.2 RD109.1 | length 186.6
  Top Layer w7: CD71.2@2517.63,3089.43 RD104.2@2577.63,3089.43 LD16.2@2577.63,3046.43 ; LD16.2@2561.63,3030.43 LD16.2@2577.63,3046.43 ; RD109.1@2622.63,3030.43 2577.63,3030.43 LD16.2@2577.63,3046.43
N09563_5444: CD51.2 LD12.2 RD74.2 RD79.1 | length 186.6
  Top Layer w7: CD51.2@2512.63,2634.43 RD74.2@2572.63,2634.43 LD12.2@2572.63,2591.43 ; LD12.2@2556.63,2575.43 LD12.2@2572.63,2591.43 ; RD79.1@2617.63,2575.43 2572.63,2575.43 LD12.2@2572.63,2591.43
N09563_5892: CD31.2 LD8.2 RD44.2 RD49.1 | length 186.6
  Top Layer w7: CD31.2@2507.63,1014.43 RD44.2@2567.63,1014.43 LD8.2@2567.63,971.43 ; LD8.2@2551.63,955.43 LD8.2@2567.63,971.43 ; RD49.1@2612.63,955.43 2567.63,955.43 LD8.2@2567.63,971.43
N09563_6340: CD11.2 LD4.2 RD14.2 RD19.1 | length 186.6
  Top Layer w7: CD11.2@2507.63,568.43 RD14.2@2567.63,568.43 LD4.2@2567.63,525.43 ; LD4.2@2551.63,509.43 LD4.2@2567.63,525.43 ; RD19.1@2612.63,509.43 2567.63,509.43 LD4.2@2567.63,525.43
N13086: CD5.1 RD3.2 RD8.1 UD3.8 | length 201.4
  Top Layer w7: CD5.1@3402.63,609.43 3402.63,610.43 RD8.1@3457.63,610.43 ; RD8.1@3457.63,609.43 RD8.1@3457.63,610.43 ; UD3.8@3517.63,635.43 3517.63,665.43 3458.63,665.43 RD3.2@3458.63,664.43 3457.63,663.43 RD8.1@3457.63,610.43
N13086_2988: CD65.1 RD93.2 RD98.1 UD15.8 | length 201.4
  Top Layer w7: CD65.1@3412.63,3130.43 3412.63,3131.43 RD98.1@3467.63,3131.43 ; RD98.1@3467.63,3130.43 RD98.1@3467.63,3131.43 ; UD15.8@3527.63,3156.43 3527.63,3186.43 3468.63,3186.43 RD93.2@3468.63,3185.43 3467.63,3184.43 RD98.1@3467.63,3131.43
N13086_5382: CD45.1 RD63.2 RD68.1 UD11.8 | length 201.4
  Top Layer w7: CD45.1@3407.63,2675.43 3407.63,2676.43 RD68.1@3462.63,2676.43 ; RD68.1@3462.63,2675.43 RD68.1@3462.63,2676.43 ; UD11.8@3522.63,2701.43 3522.63,2731.43 3463.63,2731.43 RD63.2@3463.63,2730.43 3462.63,2729.43 RD68.1@3462.63,2676.43
N13086_5830: CD25.1 RD33.2 RD38.1 UD7.8 | length 201.4
  Top Layer w7: CD25.1@3402.63,1055.43 3402.63,1056.43 RD38.1@3457.63,1056.43 ; RD38.1@3457.63,1055.43 RD38.1@3457.63,1056.43 ; UD7.8@3517.63,1081.43 3517.63,1111.43 3458.63,1111.43 RD33.2@3458.63,1110.43 3457.63,1109.43 RD38.1@3457.63,1056.43
N18557: CD78.2 RD108.1 RD115.2 UD15.4 | length 406.7
  Top Layer w7: CD78.2@3407.63,3021.43 3407.63,3026.43 3412.63,3026.43 3415.63,3023.43 RD115.2@3465.63,3023.43 3656.63,3023.43 3677.63,3002.43 UD15.4@3677.63,2960.43 3677.63,2939.43 3686.63,2930.43 RD108.1@3732.63,2930.43
N18557_5415: CD58.2 RD78.1 RD85.2 UD11.4 | length 406.7
  Top Layer w7: CD58.2@3402.63,2566.43 3402.63,2571.43 3407.63,2571.43 3410.63,2568.43 RD85.2@3460.63,2568.43 3651.63,2568.43 3672.63,2547.43 UD11.4@3672.63,2505.43 3672.63,2484.43 3681.63,2475.43 RD78.1@3727.63,2475.43
N18557_5863: CD38.2 RD48.1 RD55.2 UD7.4 | length 433.3
  Top Layer w7: CD38.2@3397.63,946.43 3397.63,951.43 3402.63,951.43 3405.63,948.43 RD55.2@3455.63,948.43 3482.63,975.37 3648.58,975.37 3667.63,956.4 3667.63,951.37 ; UD7.4@3667.63,885.43 3667.63,951.37 ; RD48.1@3719.63,986.37 3719.63,985.37 3685.63,951.37 3667.63,951.37
N18557_6311: CD18.2 RD18.1 RD25.2 UD3.4 | length 420.9
  Top Layer w7: CD18.2@3397.63,500.43 3397.63,505.43 3402.63,505.43 3405.63,502.43 RD25.2@3455.63,502.43 3469.2,516 3652.63,516 3666.2,502.43 3667.63,502.43 ; UD3.4@3667.63,439.43 3667.63,502.43 ; RD18.1@3722.63,538.37 3719.63,539.37 3682.63,502.43 3667.63,502.43
N21666: CD65.2 RD98.2 RD103.1 UD15.5 | length 414
  Top Layer w7: CD65.2@3412.63,3074.43 RD98.2@3467.63,3074.43 3467.63,3084.43 3658.63,3084.43 3677.63,3103.43 UD15.5@3677.63,3120 ; UD15.5@3677.63,3156.43 UD15.5@3677.63,3120 ; RD103.1@3733.63,3110 3742.63,3119 3741.63,3120 UD15.5@3677.63,3120
N21666_5417: CD45.2 RD68.2 RD73.1 UD11.5 | length 414.1
  Top Layer w7: CD45.2@3407.63,2619.43 RD68.2@3462.63,2619.43 3462.63,2629.43 3653.63,2629.43 3672.63,2648.43 UD11.5@3672.63,2681.43 ; UD11.5@3672.63,2701.43 UD11.5@3672.63,2681.43 ; RD73.1@3725.63,2666 3734.63,2675 3733.2,2674 3679.63,2674 UD11.5@3672.63,2681.43
N21666_5865: CD25.2 RD38.2 RD43.1 UD7.5 | length 400.1
  Top Layer w7: CD25.2@3402.63,999.43 RD38.2@3457.63,999.43 3461.63,995.37 3659.63,995.37 3667.63,1003.43 UD7.5@3667.63,1040.37 ; UD7.5@3667.63,1081.43 UD7.5@3667.63,1040.37 ; RD43.1@3719.63,1040.37 UD7.5@3667.63,1040.37
N21666_6313: CD5.2 RD8.2 RD13.1 UD3.5 | length 393.1
  Top Layer w7: CD5.2@3402.63,553.43 RD8.2@3457.63,553.43 3466.63,544 3629.7,544 3667.63,582.37 UD3.5@3667.63,604 ; UD3.5@3667.63,635.43 UD3.5@3667.63,604 ; RD13.1@3722.63,604 UD3.5@3667.63,604
N95032: CP15.2 LP4.2 UP7.1 UP7.7 UP7.8 | length 617.4
  Top Layer w7: LP4.2@733.63,201 711.63,179 LP4.2@711.3,179 LP4.2@711.3,155.33 ; v3@797.63,200 v3(798.63,201) ; CP15.2@2024.63,124 CP15.2@2044.63,104 ; v3(2104.63,104) v3@2109.63,99 ; LP4.2@711.3,155.33 736.63,130 LP4.2@711.3,155.33
  Top Layer w20: LP4.2@733.63,201 v3(798.63,201) ; CP15.2@2044.63,104 v3(2104.63,104) ; LP4.2@736.63,130 v3(799.63,130) LP4.2@736.63,130
  Bottom Layer w7: v3(2379.63,104) v3@2380.63,103 ; v3@2575.63,104 v3(2576.63,103)
  Bottom Layer w20: v3(2379.63,104) UP7.1@2454.63,104 ; v3@2575.63,104 UP7.8@2650.63,104 UP7.7@2650.63,154
N156035: RD2.1 RD4.2 UD4.1 | length 266.2
  Top Layer w7: UD4.1@2877.63,629.43 2882.63,634.43 2882.63,665.43 2886.63,669.43 RD2.1@2947.63,669.43 3002.63,614.43 RD4.2@3003.63,614.43
  Top Layer w10: UD4.1@2877.63,629.43 2877.63,707.63 2878,708 v2(2878,712)
N156035_3008: RD92.1 RD94.2 UD16.1 | length 263.3
  Top Layer w7: UD16.1@2884.63,3149 2892.63,3157 2892.63,3186.43 2896.63,3190.43 RD92.1@2957.63,3190.43 3012.63,3135.43 RD94.2@3013.63,3135.43
  Top Layer w10: v2@2884,3225 v2(2883,3224) 2884.63,3222.37 UD16.1@2884.63,3149
N156035_5406: RD62.1 RD64.2 UD12.1 | length 270.4
  Top Layer w7: UD12.1@2879.63,2694 2887.63,2702 2887.63,2731.43 2891.63,2735.43 RD62.1@2952.63,2735.43 3007.63,2680.43 RD64.2@3008.63,2680.43
  Top Layer w10: UD12.1@2879.63,2694 2880,2694.37 2880,2770 2885,2775 v2(2884,2775)
N156035_5854: RD32.1 RD34.2 UD8.1 | length 267.7
  Top Layer w7: UD8.1@2874.63,1074 2882.63,1082 2882.63,1111.43 2886.63,1115.43 RD32.1@2947.63,1115.43 3002.63,1060.43 RD34.2@3003.63,1060.43
  Top Layer w10: UD8.1@2874.63,1074 2873,1075.63 2873,1152 v2(2875,1154)
N156306: RD107.2 RD116.1 UD16.6 | length 335.3
  Top Layer w7: RD116.1@2742.63,2880.43 2746.63,2880.43 2792.63,2926.43 2792.63,2945 UD16.6@2784.63,2953 2784.63,2989 2809.63,3014 2909.63,3014 2953.2,2970.43 RD107.2@2956.63,2970.43
N156306_5416: RD77.2 RD86.1 UD12.6 | length 335.3
  Top Layer w7: RD86.1@2737.63,2425.43 2741.63,2425.43 2787.63,2471.43 2787.63,2490 UD12.6@2779.63,2498 2779.63,2534 2804.63,2559 2904.63,2559 2948.2,2515.43 RD77.2@2951.63,2515.43
N156306_5864: RD47.2 RD56.1 UD8.6 | length 335.3
  Top Layer w7: RD56.1@2732.63,805.43 2736.63,805.43 2782.63,851.43 2782.63,870 UD8.6@2774.63,878 2774.63,914 2799.63,939 2899.63,939 2943.2,895.43 RD47.2@2946.63,895.43
N156306_6312: RD17.2 RD26.1 UD4.6 | length 334.2
  Top Layer w7: RD26.1@2732.63,359.43 2736.63,359.43 2782.63,405.43 2782.63,428.43 UD4.6@2777.63,433.43 2774.63,468 2799.63,493 2899.63,493 2943.2,449.43 RD17.2@2946.63,449.43
N156577: RD22.1 RD26.2 UD4.7 | length 481.2
  Top Layer w7: UD4.7@2827.63,433.43 2827.63,397 2790.07,359.43 RD26.2@2788.63,359.43 2789.63,359.43 2789.63,358 2839.63,308 2954.63,308 2969.63,323 2969.63,372.43 RD22.1@2947.63,394.43
  Top Layer w10: v2(2724,310) 2740,324 2780,324 2788.63,332.63 RD26.2@2788.63,359.43
N156577_3005: RD112.1 RD116.2 UD16.7 | length 453.7
  Top Layer w7: RD116.2@2798.63,2880.43 RD116.2@2799.63,2880.43 ; RD116.2@2799.63,2884 RD116.2@2799.63,2880.43 ; UD16.7@2842.63,2961 UD16.7@2834.63,2953 2842.63,2945 2842.63,2922.43 2800.63,2880.43 RD116.2@2799.63,2880.43 ; RD112.1@2957.63,2915.43 2979.63,2893.43 2979.63,2844 2964.63,2829 2860,2829 2815,2874 2804.63,2874 2799.63,2879 RD116.2@2799.63,2880.43
  Top Layer w10: v2(2791,2831) 2792,2830 2792,2873.8 RD116.2@2798.63,2880.43
N156577_5401: RD82.1 RD86.2 UD12.7 | length 439.6
  Top Layer w7: RD86.2@2793.63,2425.43 RD86.2@2794.63,2425.43 ; UD12.7@2829.63,2498 2837.63,2490 2837.63,2467.43 2795.63,2425.43 RD86.2@2794.63,2425.43 ; RD82.1@2951.63,2461.43 RD82.1@2952.63,2460.43 2974.63,2438.43 2974.63,2389 2959.63,2374 2844.63,2374 2794.63,2424 RD86.2@2794.63,2425.43
  Top Layer w10: v2(2785,2375) 2785,2414 2793.63,2422.63 RD86.2@2793.63,2425.43
N156577_5849: RD52.1 RD56.2 UD8.7 | length 425.9
  Top Layer w7: RD56.2@2788.63,805.43 RD56.2@2789.63,805.43 ; UD8.7@2824.63,878 2824.63,839 2791.07,805.43 RD56.2@2789.63,805.43 ; RD52.1@2947.63,840.43 2969.63,818.43 2969.63,769 2954.63,754 2839.63,754 2789.63,804 RD56.2@2789.63,805.43
  Top Layer w10: v2(2780,762) 2790,772 2790,804.07 RD56.2@2788.63,805.43
N190647: RD99.2 UD16.3 | length 176.9
  Top Layer w7: RD99.2@2678.63,3125.43 2679.63,3125.43 2714.63,3090 2768.63,3090 2792.63,3114.43 2792.63,3141 UD16.3@2784.63,3149
N190647_5413: RD69.2 UD12.3 | length 177.8
  Top Layer w7: RD69.2@2673.63,2670.43 2674.63,2670.43 2710.63,2634 2762.63,2634 2787.63,2659.43 2787.63,2686 UD12.3@2779.63,2694
N190647_5861: RD39.2 UD8.3 | length 177.8
  Top Layer w7: RD39.2@2668.63,1050.43 2669.63,1050.43 2705.63,1014 2757.63,1014 2782.63,1039.43 2782.63,1066 UD8.3@2774.63,1074
N190647_6309: RD9.2 UD4.3 | length 176.8
  Top Layer w7: RD9.2@2668.63,604.43 2669.63,604.43 2704.63,569 2758.07,569 2782.63,594 2782.63,624.43 UD4.3@2777.63,629.43
N190660: RD19.2 UD4.5 | length 116.9
  Top Layer w7: RD19.2@2668.63,509.43 2689.63,509.43 2732.63,466.43 2732.63,438.43 UD4.5@2727.63,433.43
N190660_2989: RD109.2 UD16.5 | length 119.6
  Top Layer w7: RD109.2@2678.63,3030.43 2699.63,3030.43 2742.63,2987.43 2742.63,2961 UD16.5@2734.63,2953
N190660_5384: RD79.2 UD12.5 | length 119.6
  Top Layer w7: RD79.2@2673.63,2575.43 2694.63,2575.43 2737.63,2532.43 2737.63,2506 UD12.5@2729.63,2498
N190660_5832: RD49.2 UD8.5 | length 119.6
  Top Layer w7: RD49.2@2668.63,955.43 2689.63,955.43 2732.63,912.43 2732.63,886 UD8.5@2724.63,878
N190818: CD18.1 RD25.1 RD27.2 UD3.1 | length 235.2
  Top Layer w7: CD18.1@3397.63,444.43 3397.63,449.43 3402.63,449.43 3405.63,446.43 RD25.1@3455.63,446.43 3513.63,446.43 3517.63,442.43 UD3.1@3517.63,439.43 3517.63,402.43 3514.63,399.43 3458.63,399.43 RD27.2@3453.63,394.43
N190818_2985: CD78.1 RD115.1 RD117.2 UD15.1 | length 235.2
  Top Layer w7: CD78.1@3407.63,2965.43 3407.63,2970.43 3412.63,2970.43 3415.63,2967.43 RD115.1@3465.63,2967.43 3523.63,2967.43 3527.63,2963.43 UD15.1@3527.63,2960.43 3527.63,2923.43 3524.63,2920.43 3468.63,2920.43 RD117.2@3463.63,2915.43
N190818_5380: CD58.1 RD85.1 RD87.2 UD11.1 | length 235.2
  Top Layer w7: CD58.1@3402.63,2510.43 3402.63,2515.43 3407.63,2515.43 3410.63,2512.43 RD85.1@3460.63,2512.43 3518.63,2512.43 3522.63,2508.43 UD11.1@3522.63,2505.43 3522.63,2468.43 3519.63,2465.43 3463.63,2465.43 RD87.2@3458.63,2460.43
N190818_5828: CD38.1 RD55.1 RD57.2 UD7.1 | length 235.2
  Top Layer w7: CD38.1@3397.63,890.43 3397.63,895.43 3402.63,895.43 3405.63,892.43 RD55.1@3455.63,892.43 3513.63,892.43 3517.63,888.43 UD7.1@3517.63,885.43 3517.63,848.43 3514.63,845.43 3458.63,845.43 RD57.2@3453.63,840.43
N191405: RA23.2 RA24.1 RA25.1 RA26.1 UA3.3 | length 460.9
  Top Layer w7: RA23.2@3012.63,1919.43 3013.63,1920.43 RA24.1@3057.63,1920.43 ; RA26.1@3057.63,2030.43 RA25.1@3057.63,1975.43 RA24.1@3057.63,1920.43 ; UA3.3@3233.83,1945.43 3233.83,1980.23 3222.63,1991.43 3169.63,1991.43 3161.63,1983.43 3161.63,1946.43 3142.63,1927.43 3142.63,1902.43 3133.63,1893.43 3081.63,1893.43 3057.63,1917.43 RA24.1@3057.63,1920.43
N191965: CP11.2 UP3.3 | length 77
  Bottom Layer w7: UP3.3@2192.63,3337.8 2262.83,3337.8 CP11.2@2267.63,3333
N192118: RP14.2 RP15.1 UP3.2 | length 201
  Bottom Layer w7: UP3.2@2192.63,3363.4 2241.23,3363.4 2244.63,3360 2296.63,3360 2324.63,3332 RP14.2@2324.63,3331 RP15.1@2379.63,3331
N192153: CP13.1 LP3.2 RP16.1 UP3.8 | length 504.5
  Top Layer w7: LP3.2@756.3,3394 756.3,3435.67 794.63,3474 v2(869.63,3474)
  Top Layer w20: CP13.1@1619.63,3504 v2(1694.63,3504) CP13.1@1619.63,3504
  Bottom Layer w7: 1999.73,3446.1 RP16.1@2002.63,3449
  Bottom Layer w20: v2(1933.63,3504) 2000,3504 2000,3451.63 RP16.1@2002.63,3449 ; UP3.8@1999.73,3389 1999.73,3446.1
  other v1: 2001,3502
  other v2: 868.63,3554
N192759: CP3.2 RP3.2 UP1.5 UP2.5 UP3.5 UP7.6 | length 6723.9
  Top Layer w7: RP3.2@1094.63,1270 1094.63,1381 1112.63,1399 v1(1227.63,1399) ; UP2.5@2139.73,1500.75 2140.63,1501.65 v1(2140.63,1545)
  Mid-Layer 1 w7: v1(1227.63,1399) 1227.63,561.93 1221.13,555.43 1221.13,520.43 1227.63,513.93 1227.63,183.93 1273.63,137.93 2509.57,137.93 v1(2556.63,185)
  Mid-Layer 2 w7: v1(2050.63,3281) 1687.63,3281 1664.63,3304 1589.63,3304 1194.63,2909 1194.63,1434 1229.63,1399 v1(1227.63,1399) 1228.63,1398 1476.63,1398 1607,1528.37 2124,1528.37 v1(2140.63,1545)
  Bottom Layer w7: v1(1227.63,1399) 1254.38,1372.25 UP1.5@1296.73,1372.25 1296.73,1341.9 CP3.2@1316.63,1322 ; v1(2556.63,185) 2556.63,187 2557.63,188 2583.63,188 2599.63,204 UP7.6@2650.63,204
  Bottom Layer w15: UP3.5@1999.73,3312.25 2026.75,3312.25 2050.63,3288.37 v1(2050.63,3281)
N193110: CP6.1 LP1.2 RP7.1 UP1.8 | length 578.5
  Top Layer w7: v2@658.63,1806 v2(659.63,1805) ; LP1.2@715.63,1806 746.3,1775.33 LP1.2@746.3,1769.67 ; LP1.2@746.3,1748.37 LP1.2@746.3,1769.67 ; v1(1296.63,1482) 1309.63,1495 CP6.1@1309.63,1599 ; LP1.2@746.3,1769.67 780.63,1804 LP1.2@746.3,1769.67
  Top Layer w20: v2@658.63,1806 LP1.2@715.63,1806 ; LP1.2@780.63,1804 v2(839.63,1804) LP1.2@780.63,1804
  Bottom Layer w7: UP1.8@1296.73,1449 1296.73,1481.9 v1(1296.63,1482) 1323.63,1509 RP7.1@1364.63,1509
N193130: RP5.2 RP6.1 UP1.2 | length 115.4
  Bottom Layer w7: UP1.2@1489.63,1423.4 1527.03,1423.4 1554.63,1451 ; RP6.1@1554.63,1449 1554.63,1451 ; RP5.2@1554.63,1488 1554.63,1451
N195694: RA17.1 UA3.9 | length 43.2
  Top Layer w7: UA3.9@3361.77,2179.68 3367.52,2185.43 RA17.1@3402.63,2185.43
N195704: RA27.1 UA3.7 | length 160.1
  Top Layer w7: UA3.7@3336.23,1945.43 3336.23,1989.03 3342.63,1995.43 3372.63,1995.43 3402.63,1965.43 RA27.1@3402.63,1930.43
N195714: RA12.2 RA14.2 RA15.2 RA16.2 UA3.13 | length 526
  Top Layer w7: RA12.2@3012.63,2195.43 3052.63,2195.43 RA15.2@3056.63,2191.43 ; RA14.2@3056.63,2085.43 RA16.2@3056.63,2140.43 RA15.2@3056.63,2191.43 ; RA15.2@3056.63,2195.43 RA15.2@3056.63,2193.43 ; UA3.13@3259.4,2179.68 3259.4,2137.2 3220.63,2098.43 3185.63,2098.43 3178.63,2105.43 3178.63,2124.43 3162.63,2140.43 3162.63,2199.43 3139.63,2222.43 3085.63,2222.43 RA15.2@3056.63,2193.43 ; RA15.2@3056.63,2191.43 RA15.2@3056.63,2193.43
N195717: RD92.2 RD95.2 RD96.2 RD97.2 UD14.13 | length 520.6
  Top Layer w7: RD92.2@3013.63,3190.43 RD95.2@3056.63,3190.43 ; RD97.2@3056.63,3080.43 RD96.2@3056.63,3135.43 RD95.2@3056.63,3190.43 ; UD14.13@3259.38,3174.02 3259.38,3129.18 3221.63,3091.43 3192.63,3091.43 3161.63,3122.43 3161.63,3192.43 3136.63,3217.43 3083.63,3217.43 RD95.2@3056.63,3190.43
N195717_5425: RD62.2 RD65.2 RD66.2 RD67.2 UD10.13 | length 520.6
  Top Layer w7: RD62.2@3008.63,2735.43 RD65.2@3051.63,2735.43 ; RD67.2@3051.63,2625.43 RD66.2@3051.63,2680.43 RD65.2@3051.63,2735.43 ; UD10.13@3254.38,2719.02 3254.38,2674.18 3216.63,2636.43 3187.63,2636.43 3156.63,2667.43 3156.63,2737.43 3131.63,2762.43 3078.63,2762.43 RD65.2@3051.63,2735.43
N195717_5873: RD32.2 RD35.2 RD36.2 RD37.2 UD6.13 | length 520.6
  Top Layer w7: RD32.2@3003.63,1115.43 RD35.2@3046.63,1115.43 ; RD37.2@3046.63,1005.43 RD36.2@3046.63,1060.43 RD35.2@3046.63,1115.43 ; UD6.13@3249.38,1099.02 3249.38,1054.18 3211.63,1016.43 3182.63,1016.43 3151.63,1047.43 3151.63,1117.43 3126.63,1142.43 3073.63,1142.43 RD35.2@3046.63,1115.43
N195717_6321: RD2.2 RD5.2 RD6.2 RD7.2 UD2.13 | length 520.6
  Top Layer w7: RD2.2@3003.63,669.43 RD5.2@3046.63,669.43 ; RD7.2@3046.63,559.43 RD6.2@3046.63,614.43 RD5.2@3046.63,669.43 ; UD2.13@3249.38,653.02 3249.38,608.18 3211.63,570.43 3182.63,570.43 3151.63,601.43 3151.63,671.43 3126.63,696.43 3073.63,696.43 RD5.2@3046.63,669.43
N195917: RA11.1 RA19.2 UA2.4 | length 418.9
  Top Layer w7: RA19.2@2737.63,2091.43 2769.63,2091.43 2792.63,2114.43 UA2.4@2792.63,2115.43 ; v2(2747,2181) 2777.57,2150.43 UA2.4@2792.63,2150.43 UA2.4@2792.63,2115.43 ; RA11.1@3021.63,2040.43 RA11.1@3012.63,2040.43 2988.63,2040.43 2936.63,2092.43 2815.63,2092.43 UA2.4@2792.63,2115.43
N195920: RA11.2 RA12.1 UA2.1 | length 117.6
  Top Layer w7: UA2.1@2942.63,2150.43 2953.63,2139.43 RA12.1@3012.63,2139.43 RA11.2@3012.63,2096.43
N195926: RA22.2 RA23.1 UA2.8 | length 163.1
  Top Layer w7: UA2.8@2942.63,1954.43 UA2.8@2943.63,1953.43 ; RA22.2@2943.63,1880.43 UA2.8@2943.63,1953.43 ; RA23.1@3012.63,1975.43 2947.63,1975.43 2943.63,1971.43 UA2.8@2943.63,1953.43
N195932: RA21.2 RA22.1 UA2.5 | length 229.3
  Top Layer w7: v2(2782,2039) 2792.63,2028.37 UA2.5@2792.63,1954.43 2792.63,1929.43 2841.63,1880.43 RA21.2@2843.63,1880.43 RA22.1@2887.63,1880.43
N195968: CA1.1 UA1.20 UA2.2 UA4.2 | length 2117.8
  Top Layer w7: UA1.20@2037.72,2087.85 2037.72,2121.82 2214.34,2298.43 2592.63,2298.43 2632.63,2258.43 CA1.1@2632.63,2255.43 2644.63,2267.43 2648.07,2267.43 2678.07,2297.43 2966.63,2297.43 2977.63,2286.43 ; UA2.2@2892.63,2150.43 2892.63,2195.43 2906.63,2209.43 2941.63,2209.43 2966.63,2234.43 2966.63,2275.43 2977.63,2286.43 ; UA4.2@3617.63,2165.43 3617.63,2198.43 3650.63,2231.43 3650.63,2278 3600.2,2328.43 3019.63,2328.43 2977.63,2286.43
N196007: CA11.2 CA12.2 CA13.2 UA1.13 UA1.14 | length 247.2
  Top Layer w7: UA1.13@2123.35,2002.22 2144.27,2002.22 2144.27,2021.91 ; UA1.14@2123.35,2021.91 2144.27,2021.91 ; CA12.2@2201.73,2021.91 2144.27,2021.91 ; CA12.2@2201.77,2021.87 CA13.2@2265.2,2021.87 ; CA13.2@2269.63,2017.43 2271.63,2015.43 CA11.2@2333.63,2015.43
N196017: CA12.1 CA13.1 CA14.2 UA1.11 UA1.12 | length 278.1
  Top Layer w7: UA1.11@2123.35,1962.85 2144.27,1962.85 ; UA1.12@2123.35,1982.54 2144.27,1982.54 2144.27,1962.85 ; CA14.2@2333.63,1935.43 2331.63,1933.43 CA13.1@2269.63,1933.43 2214.2,1933.43 2201.77,1945.87 CA12.1@2201.77,1965.87 2147.29,1965.87 2144.27,1962.85
N196076: CA20.1 CA21.1 CA22.2 UA1.3 UA1.4 | length 275.2
  Top Layer w7: UA1.3@2123.35,1805.37 2144.27,1805.37 ; UA1.4@2123.35,1825.06 2144.27,1825.06 2144.27,1805.37 ; CA22.2@2332.63,1775.43 CA21.1@2267.63,1775.43 2209.7,1775.43 2201.73,1783.41 CA20.1@2201.73,1805.37 2144.27,1805.37
N196084: CA19.2 CA20.2 CA21.2 UA1.5 UA1.6 | length 252.3
  Top Layer w7: UA1.5@2123.35,1844.74 2144.27,1844.74 2144.27,1864.43 ; UA1.6@2123.35,1864.43 2144.27,1864.43 ; CA21.2@2264.63,1856.43 CA21.2@2267.63,1859.43 2328.63,1859.43 CA19.2@2330.63,1857.43 ; CA21.2@2265.7,1861.37 CA20.2@2201.73,1861.37 2147.32,1861.37 2144.27,1864.43
N196646: RA1.2 RA2.2 UA1.21 | length 176.4
  Top Layer w7: RA2.2@1985.77,2208.37 v4(1985.77,2165.87) 1985.77,2151.87 2018.03,2119.6 UA1.21@2018.03,2087.85
  Bottom Layer w7: v4(1985.77,2165.87) RA1.2@1985.77,2208.37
